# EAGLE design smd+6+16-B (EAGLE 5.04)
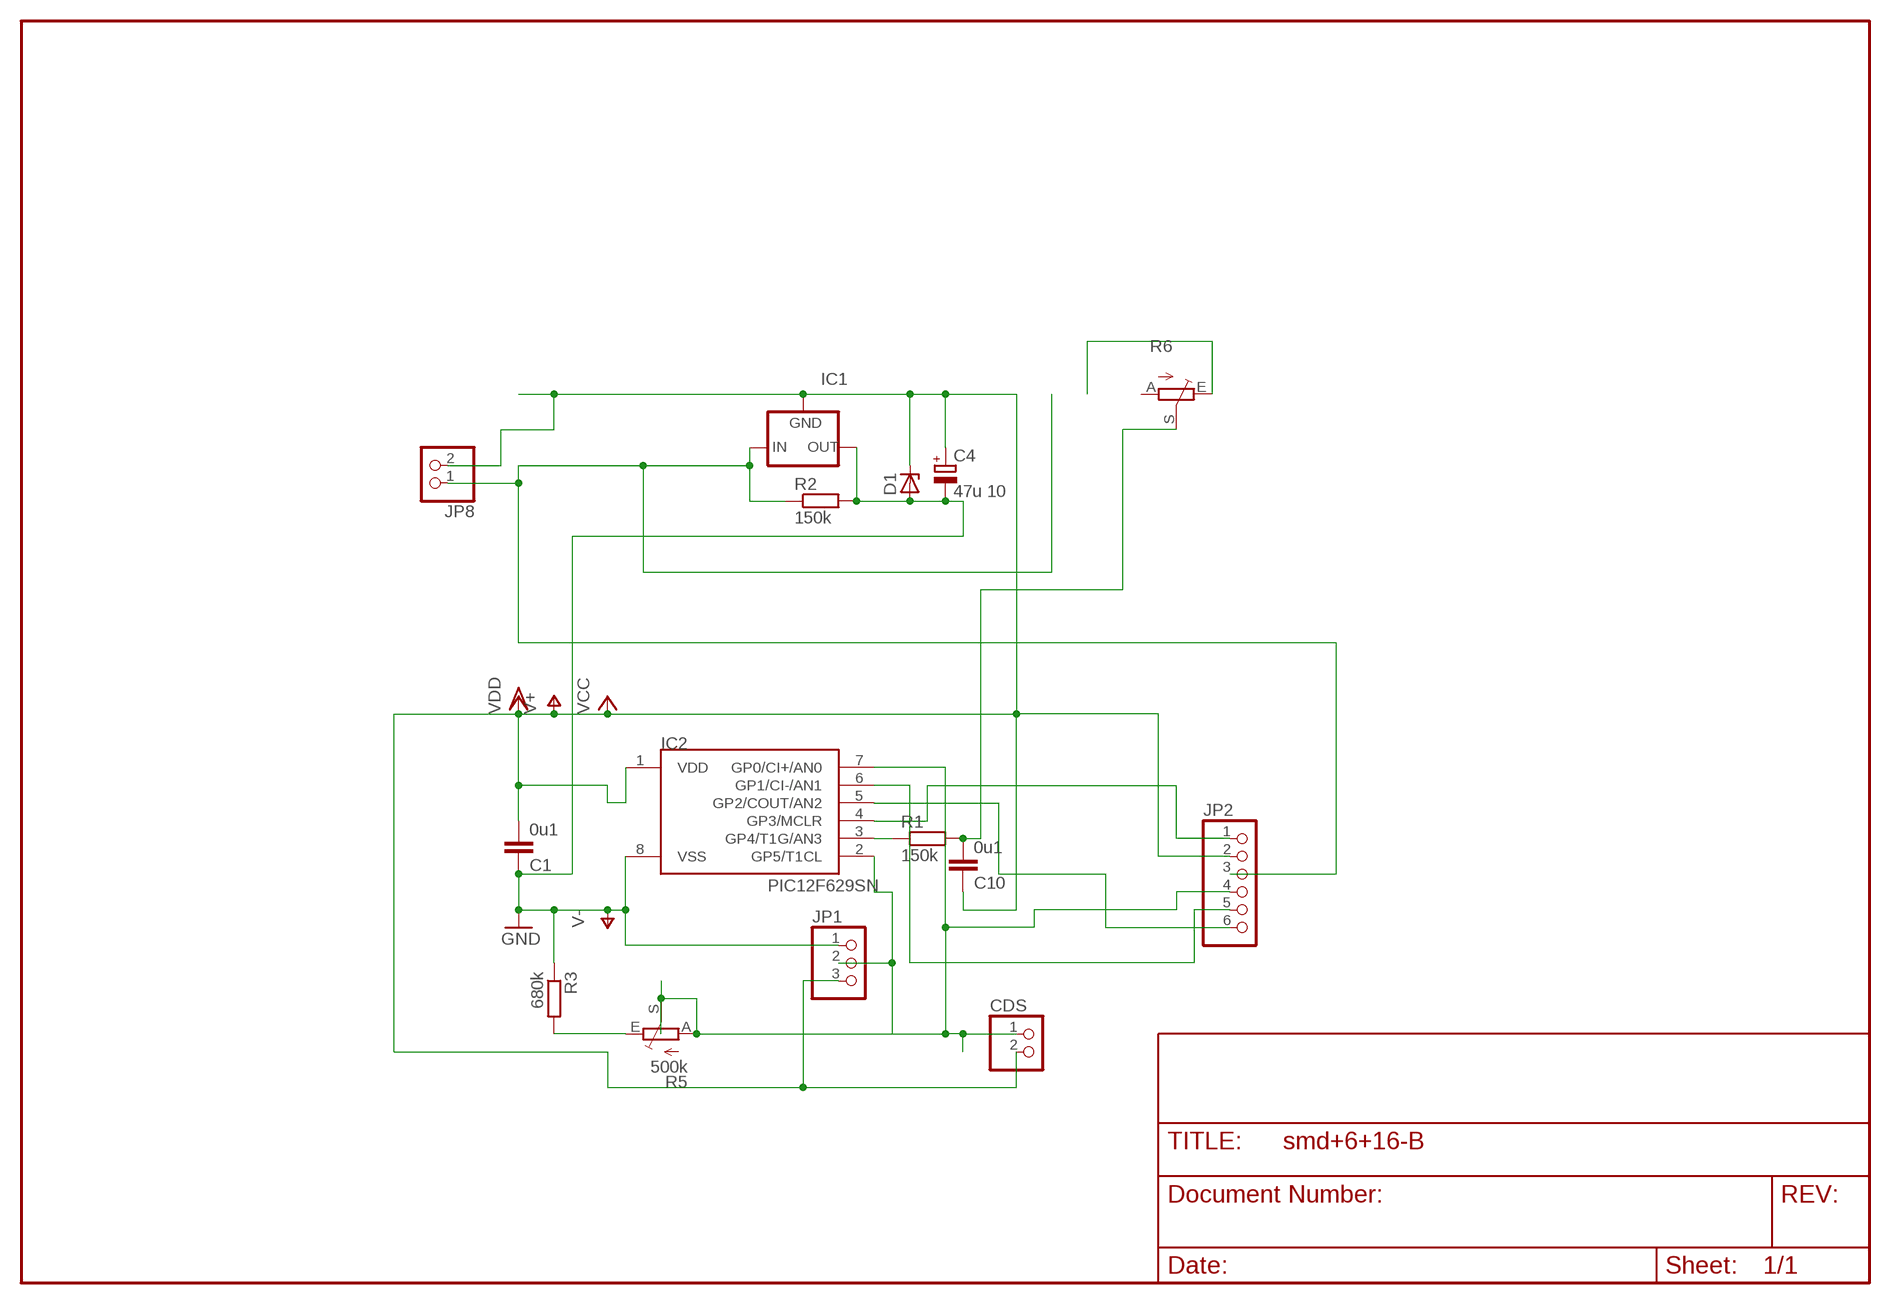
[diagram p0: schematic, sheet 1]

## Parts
C1  0u1  C-EUC1206  [C1206]
C4  47u 10  CPOL-EUE2.5-6  [E2,5-6]
C10  0u1  C-EUC1206  [C1206]
CDS  PINHD-1X2  [1X02]
D1  ZENER-DIODESOT23  [SOT23]
IC1  79LXX  [79LXX]
IC2  PIC12F629SN  [SO-08]
JP1  PINHD-1X3  [1X03]
JP2  PINHD-1X6  [1X06]
JP8  PINHD-1X2  [1X02]
R1  150k  R-EU_R0805  [R0805]
R2  150k  R-EU_0204/2V  [0204V]
R3  680k  R-EU_R1206  [R1206]
R5  500k  TRIM_EU-CA6V  [CA6V]
R6  TRIM_EU-CA6V  [CA6V]

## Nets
CDS: IC2.2(GP5/T1CL) JP1.2
N$1: C10.2 R1.2 R6.S
N$2: IC2.5(GP2/COUT/AN2) JP2.6
N$3: IC2.4(GP3/MCLR) JP2.1
N$4: CDS.1 IC2.7(GP0/CI+/AN0) JP2.4 R5.A R5.S
N$5: R3.2 R5.E
N$7: R6.E
N$8: IC2.3(GP4/T1G/AN3) R1.1
N$10: IC1.IN JP2.3 JP8.1 R2.1
N$15: IC2.6(GP1/CI-/AN1) JP2.5
V+: C1.2 C4.+ C10.1 CDS.2 D1.3(C) IC1.GND IC2.1(VDD) JP1.3 JP2.2 JP8.2 ; supply symbol labelled VCC, VDD
V-: C1.1 C4.- D1.1(A) IC1.OUT IC2.8(VSS) JP1.1 R2.2 R3.1 ; supply symbol labelled GND
Unconnected: R6.A

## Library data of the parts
C1 C10 = rcl:C-EU: CAPACITOR, European symbol
C4 = rcl:CPOL-EU: POLARIZED CAPACITOR, European symbol
CDS JP8 = pinhead:PINHD-1X2: PIN HEADER
D1 = diode-1:ZENER-DIODE: Z-Diode
IC1 = v-reg:79LXX: VOLTAGE REGULATOR
IC2 = microchip-3:PIC12F6*: uPC nW 1k Program Flash memory 2x Timer Comparator 10b A/D converter/ 4xIN
JP1 = pinhead(2):PINHD-1X3: PIN HEADER
JP2 = pinhead:PINHD-1X6: PIN HEADER
R1-R3 = rcl:R-EU_: RESISTOR, European symbol
R5 R6 = pot:TRIM_EU-: POTENTIOMETER

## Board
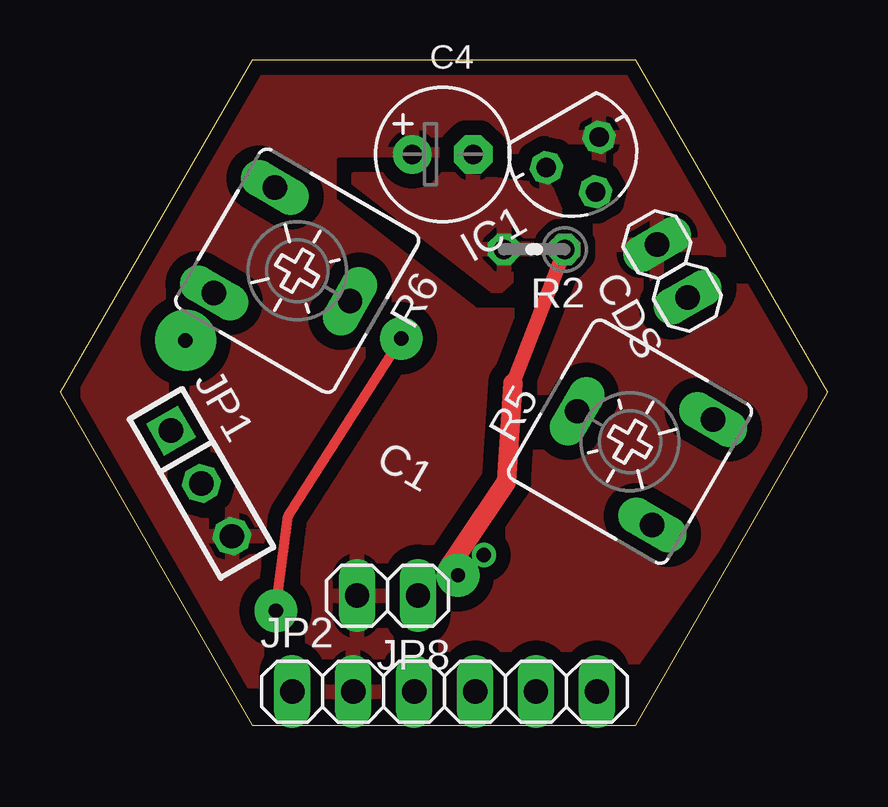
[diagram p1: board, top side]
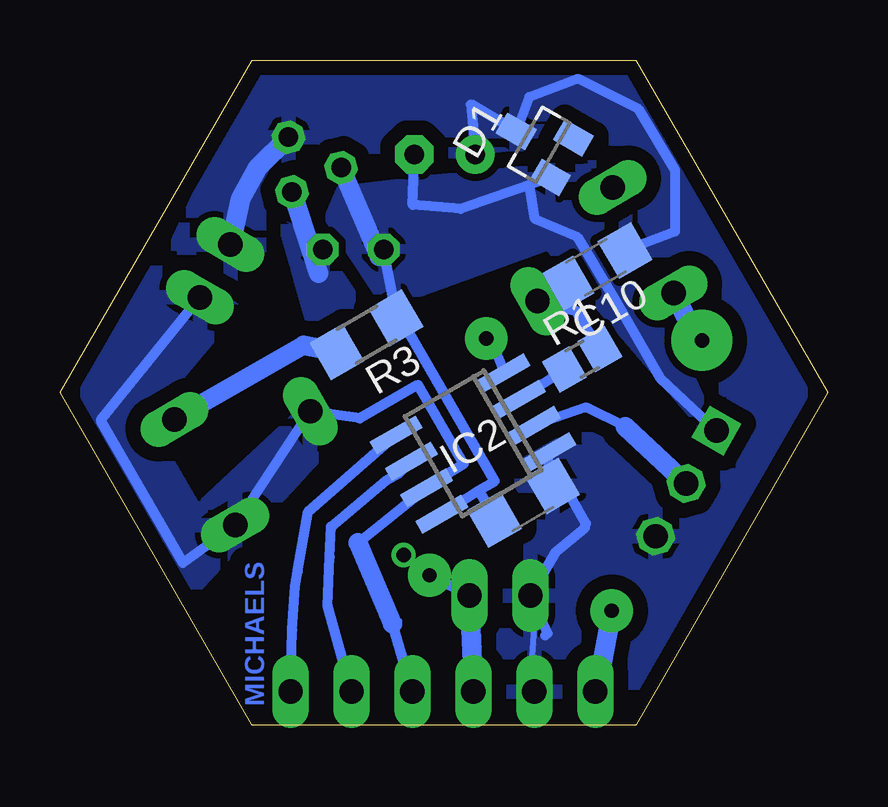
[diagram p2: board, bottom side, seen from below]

Size 32 x 27.71 mm. Coordinates in mm from the lower left corner, seen from the top.
Outline: 8,0 24,0 32,13.86 24,27.71 8,27.71 0,13.86 8,0
Copper layers (1*16): Top 0.035mm / dielectric 1.5mm / Bottom 0.035mm
Design rules "default *": minimum track width 10mil, minimum drill 24mil, track to track 8mil, track to pad 8mil, pad to pad 8mil, via to via 8mil, smd to smd 8mil, copper to edge 10mil, drill to drill 8mil, minimum pad ring 10mil, minimum via ring 8mil, stop-mask expansion 4mil, vias tented up to drill 0mil, thermal gap 10mil

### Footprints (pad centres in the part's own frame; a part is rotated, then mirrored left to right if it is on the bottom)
C1206 = smd 1.6 x 1.8: 1 -1.4,0; 2 1.4,0
E2,5-6 = drill 0.813 pad 1.6 round: + -1.27,0 | drill 0.813 pad 1.6 octagon: - 1.27,0
1X02 = drill 1.016 long: 1 -1.27,0; 2 1.27,0
SOT23 = smd 1 x 1.4: 1 -0.95,-1.1; 2 0.95,-1.1; 3 0,1.1
79LXX = drill 0.813 octagon: GND -1.27,0; IN 0,1.905; OUT 1.27,0
SO-08 = smd 0.6 x 2.2: 1 -1.905,-2.6; 2 -0.635,-2.6; 3 0.635,-2.6; 4 1.905,-2.6; 5 1.905,2.6; 6 0.635,2.6; 7 -0.635,2.6; 8 -1.905,2.6
1X03 = drill 1.016 square: 1 -2.54,0 | drill 1.016 octagon: 2 0,0; 3 2.54,0
1X06 = drill 1.016 long: 1 -6.35,0; 2 -3.81,0; 3 -1.27,0; 4 1.27,0; 5 3.81,0; 6 6.35,0
R0805 = smd 1.3 x 1.5: 1 -0.85,0; 2 0.85,0
0204V = drill 0.813 octagon: 1 -1.27,0; 2 1.27,0
R1206 = smd 1.6 x 1.803: 1 -1.422,0; 2 1.422,0
CA6V = drill 1.016 long: A -2.54,-2.54; E 2.54,-2.54; S 0,2.54

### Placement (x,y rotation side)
C1  12.67,9.27 30 bottom
C4  15.96,23.78 0 top
C10  9.65,19.08 210 bottom
CDS  25.53,18.92 120 top
D1  12.03,24.19 60 bottom
IC1  21.38,23.86 210 top
IC2  14.78,11.74 120 bottom
JP1  5.9,10.07 300 top
JP2  16.04,1.39 0 top
JP8  13.65,5.39 180 top
R1  10.23,15.24 30 bottom
R2  19.77,19.82 180 top
R3  19.23,16.26 210 bottom
R5  23.77,11.8 60 top
R6  9.89,18.93 240 top

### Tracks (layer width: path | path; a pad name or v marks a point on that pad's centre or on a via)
CDS
  Bottom 0.406: 8.43,12.42 10.07,13.23 IC2.2
  Bottom 0.813: JP1.2 8.43,12.42
N$1
  Bottom 0.406: R1.2 10.48,17.25 R6.S 11.97,17.73 C10.2
N$2
  Bottom 0.406: IC2.5 21.65,8.89 22.09,6.4 22.2,5.79 22.32,3.96 JP2.6
N$3  (via drill 0.6 pad 1.78)
  Top 0.406: v14.23,16.11 9.52,8.71 v9,4.76
  Bottom 0.254: JP2.1 9.17,2.02 9.5,2.08
  Bottom 0.406: IC2.4 13.99,15.96 v14.23,16.11
  Bottom 0.813: v9,4.76 9.5,2.08 9.64,1.31
N$4
  Bottom 0.254: 18.14,4.22 17.85,4.34
  Bottom 0.406: 19.58,7.6 IC2.7 15.94,10.43 15.17,10.88 17.07,14.18 19.49,12.78 R5.S R5.A 26.87,6.76 30.3,12.7 CDS.1 | JP2.4 18.14,4.22
  Bottom 0.813: 18.14,4.22 19.58,7.6
  pour Bottom (isolate 0.61): 28.06,18.98 31.47,13.2 26.67,5.41 20.37,12.27 21.35,13.46 26.31,8.84 28.6,12.8 24.77,17.36
N$5
  Bottom 0.813: R3.2 21.84,15.82 R5.E
N$7
  Bottom 0.813: 5.41,16.07 R6.E
N$8
  Bottom 0.406: IC2.3 11.51,14.45 R1.1
N$9  (via drill 0.6)
  other vias: 17.67,7.09
N$10  (via drill 0.6 pad 1.78)
  Top 0.61: 18.88,14.24 R2.1
  Top 0.813: 18.88,14.24 18.62,10.13 16.16,6.49 v16.6,6.24
  Bottom 0.254: JP2.3 14.84,1.68 14.75,1.68
  Bottom 0.406: R2.1 21.22,18.82 | JP8.1 v16.6,6.24 16.16,6.49
  Bottom 0.813: JP8.1 14.75,1.68 14.76,1.29 | 21.22,18.82 IC1.IN
  pour Bottom (isolate 0.61): 22.58,20.67 21.16,19.73 19.16,16.78 21.43,16.65
N$11  (via drill 0.6 pad 2.54)
  other vias: 5.23,16.03
N$15
  Bottom 0.254: JP2.5 19.41,1.97 | 20.75,7 20.85,7.01
  Bottom 0.406: IC2.6 17.88,10.49 18.42,10.17 20.7,8.27 20.75,7 20.84,4.96 JP2.5
V+
  Bottom 0.254: JP2.2 12.01,1.85 12.3,2.86 12.18,4.68 JP8.2
  Bottom 0.406: IC2.1 11.65,11.14 C1.2 11.02,10.04 10.07,8.39 10.11,8.22 11.31,7.24 JP8.2 11.67,3.8 11.78,3.74 | C4.+ 14.87,25.86 D1.3 12.45,26.16 10.41,26.92 7.87,25.65 6.35,23.11 6.35,20.57 C10.1
  Bottom 0.813: CDS.2 24.48,21.93 23.76,23.22 IC1.GND
  pour Bottom (isolate 0.61, rank 6): 30.02,13.74 22.4,0.54 8.19,0.83 0.34,14.16 8.34,28.01 23.78,27.32
  pour Top (isolate 0.61, rank 6): 31.43,13.34 22.4,0.54 8.19,0.83 0.22,13.94 8.27,27.68 23.83,27.2
V-
  Bottom 0.406: 14.53,9.78 IC2.8 | C1.1 13.77,8.46 14.53,9.78 | R2.2 18.7,19.54 | 18.07,17.6 R2.2 | 18.07,17.6 17.92,16.91 | 12.42,22.51 D1.1 | 12.42,22.51 15.29,21.51 17.29,21.67 C4.- | R2.2 19.02,20.09 | 14.53,9.78 13.87,10.16 17.43,16.32 18.04,17.32 | JP1.1 6.96,14.44 8.89,17.78 10.41,20.32 12.19,21.08 12.42,22.51 | 18.04,17.32 18.07,17.6 | 18.04,17.32 R3.1
  Bottom 0.813: 18.7,19.54 IC1.OUT
  pour Bottom (isolate 0.305, rank 2): 20.29,22.29 16.45,22.75 9.77,23.38 4.4,11.52 11.62,19.97 18.41,17.51 20.79,21.12
  pour Top (isolate 0.61, rank 2): 20.29,22.29 16.45,22.75 12.35,22.77 18.22,18.2 20.03,19.8 20.79,21.12

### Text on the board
Bottom: MICHAELS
